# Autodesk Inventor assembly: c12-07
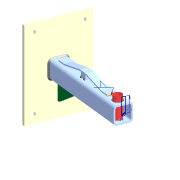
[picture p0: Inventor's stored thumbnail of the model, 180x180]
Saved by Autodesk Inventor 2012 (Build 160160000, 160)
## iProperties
Created: 2011-01
Part Number: c12-07
Document SubType Name: Weldment
Designer: Beta-8540w
Weld Material: Welded Steel Mild
_SolveAssemblyDoc: Frame Generator Solve Assembly
_Version: 15.0.0
Author: Beta-8540w
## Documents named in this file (5)
- C:\Users\VMuser\Desktop\Inventor 2012 Essentials\Assemblies\Chapter 12\c12-07.iam
- C:\Users\VMuser\Desktop\Inventor 2012 Essentials\Parts\Chapter 12\c12-01.ipt
- C:\Users\VMuser\Desktop\Inventor 2012 Essentials\Parts\Chapter 12\c12-02.ipt
- C:\Users\VMuser\Desktop\Inventor 2012 Essentials\Assemblies\Chapter 12\Frame\Frame c12-01.iam
- C:\Users\VMuser\Desktop\Inventor 2012 Essentials\Parts\Chapter 12\c12-03.ipt
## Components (4 placed, 4 different names)
1. c12-01:1 — Mate:2
2. c12-02:1 — Flush:1
3. Frame c12-01:1 [sub-assembly] — Mate:3
4. c12-03:1 — Mate:1, Mate:2, Mate:3
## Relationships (4: Mate 3, Flush 1)
- Flush:1: c12-02:1
- Mate:1: c12-03:1
- Mate:2: c12-01:1 ↔ c12-03:1
- Mate:3: Frame c12-01:1 ↔ c12-03:1
